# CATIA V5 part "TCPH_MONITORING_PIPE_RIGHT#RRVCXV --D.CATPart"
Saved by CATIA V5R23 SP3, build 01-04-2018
Part number: TCPH_MONITORING_PIPE_RIGHT#RRVCWD
Revision: --D
Nomenclature: _
Description: TCPH_MONITORING_PIPE_RIGHT
Property "AT": "PD"
Property "REP": "CM"
Property "External Part ID": "_"
Property "Description Modification": "_"
Property "PREF": "Y"
Property "LONG": "_"
Property "PBS 1": "24"
Property "PBS 2": "CR"
Property "PBS 3": "LC"
Property "DEPT": "_"
Property "DIVN": "_"
Property "GROUP": "_"
Property "UNIT": "_"
Property "PARTY": "_"
Property "RO": "IOKIK"
Property "RE": "VITUPIG"
Property "PRO": "---"
Property "Change Type": "Minor"
Property "Maturity Level": "CD"
Property "Export Number": "_"
Property "Description Documents": "_"
Property "BOM": "_"
Property "ID": "RRVCWD"
Property "User In Enovia": "VAUQUEJ"
Property "Object Type": "_"
Property "CADENAS_ID": "_"
Property "Life Cycle Status": "Approved"
Material "X2CrNi18-09 1.4307 (304L)": density 8000 kg/m3, Young's modulus 1.93e+11 Pa, Poisson ratio 0.3, thermal expansion 1.6e-05 1/K
Bounding box of the stored display mesh (mm): x 13037 to 14145, y 685 to 993, z -4396 to -3360
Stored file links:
  C:\Users\pandeym\Desktop\__TCPH\TCPH_MONITORING_PIPE_RIGHT#RRVCXV --D.CATPart
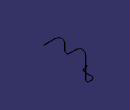
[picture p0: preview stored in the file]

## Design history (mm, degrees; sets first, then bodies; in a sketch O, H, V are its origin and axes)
TTRSSet1
f4a2d38f3ddc11d3a929006094b99c4b_11 "CATTPSSet"
Set1
  DatumCurve1 "MONITORING_PIPE_PROFIL": linked copy from another document
  Sketch1 "MONITORING_PIPE_SECTION", origin (0, 685, 0), H (-1, 0, 0), V (0, 0, 1), geometry linked from another document
Body1 (main body)
  Rib1: profile Sketch1, centre curve DatumCurve1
